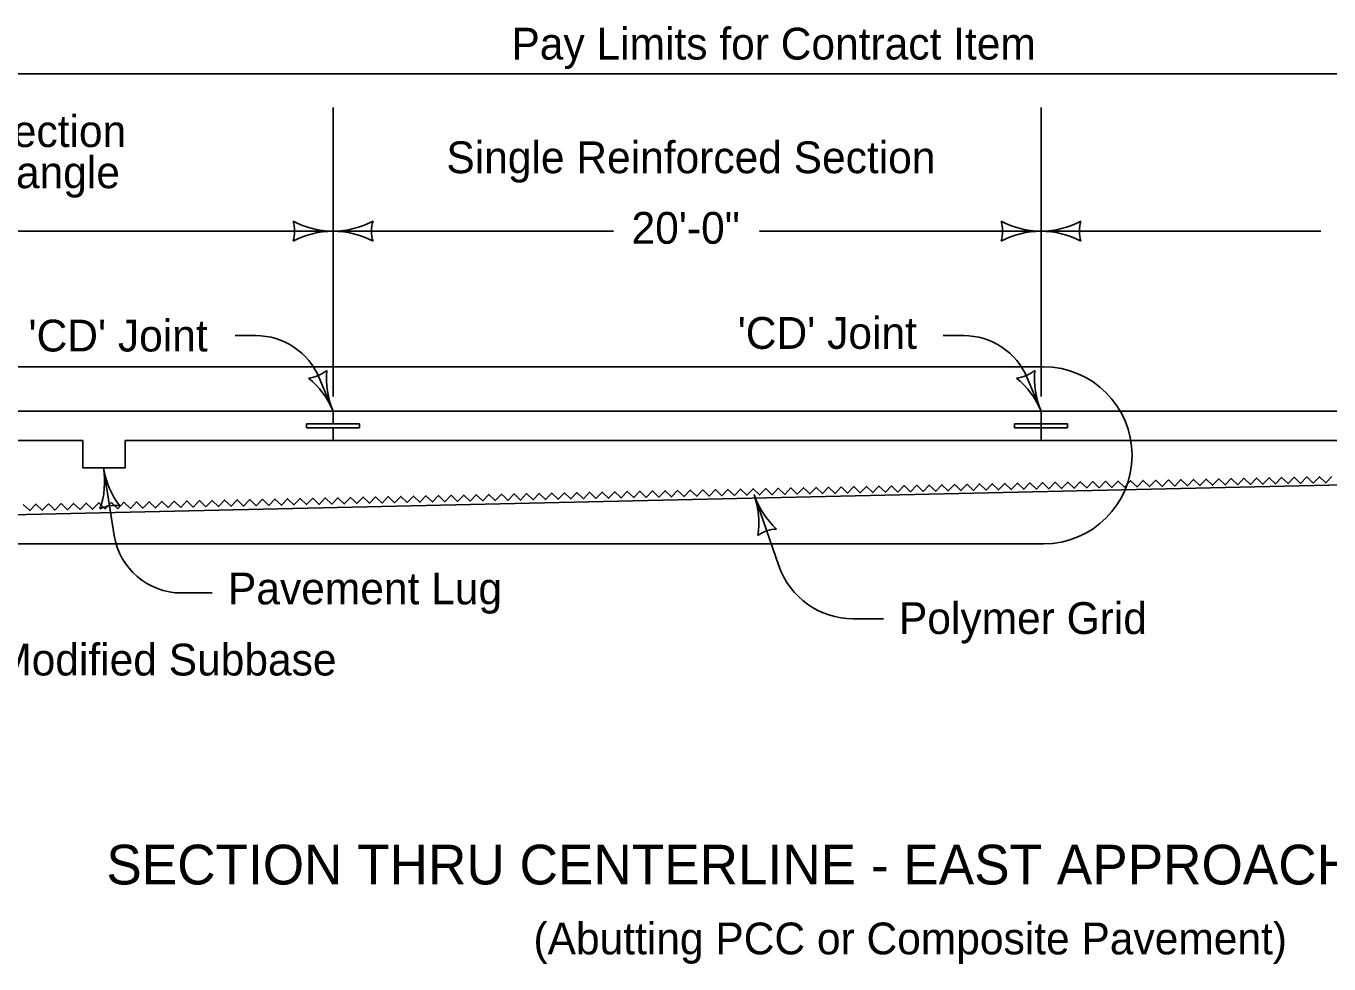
# Model space of a CAD drawing. Extents: x 5546 to 81668, y 3174 to 15999.
# Drawn here: x 14429 to 15084, y 8936 to 9408 of the extents above; entities that cross this region are included whole.
import ezdxf

# ---------------------------------------------------------------- set-up
doc = ezdxf.new("R2010")
doc.units = 0
for name, color, linetype in [('PS_BOLT', 7, 'Continuous'), ('PS_CONST', 7, 'Continuous'), ('PS_DAWA', 7, 'Continuous'), ('PS_DIM', 7, 'Continuous'), ('PS_SHAPE', 7, 'Continuous')]:
    doc.layers.add(name, color=color, linetype=linetype)

msp = doc.modelspace()

# ---------------------------------------------------------------- linework, layer by layer
at = {"layer": 'PS_BOLT'}
for p, q in [((14137.63, 9214.55), (14583.13, 9214.56)), ((14583.13, 9214.56), (14583.13, 9208.07)), ((14583.13, 9208.07), (14583.13, 9214.56)), ((14583.13, 9214.56), (14939.53, 9214.56)), ((14939.53, 9214.56), (14939.53, 9208.06)), ((14583.13, 9208.07), (14569.76, 9208.06)), ((14569.76, 9208.06), (14583.13, 9208.07)), ((14569.76, 9208.06), (14569.76, 9206.2)), ((14596.49, 9208.06), (14569.76, 9208.06)), ((14569.76, 9208.06), (14569.76, 9206.2)), ((14569.76, 9206.2), (14583.11, 9206.2)), ((14583.11, 9206.2), (14583.13, 9199.71)), ((14583.13, 9199.71), (14583.11, 9206.2)), ((14596.49, 9208.06), (14583.13, 9208.06)), ((14583.13, 9206.17), (14596.49, 9206.2)), ((14596.49, 9206.2), (14596.49, 9208.06)), ((14596.49, 9206.2), (14596.49, 9208.06)), ((14939.53, 9208.06), (14926.16, 9208.06)), ((14926.16, 9208.06), (14926.16, 9206.2)), ((14926.16, 9206.2), (14939.53, 9206.2)), ((14939.53, 9206.2), (14939.53, 9199.71)), ((14939.53, 9199.71), (14583.13, 9199.71))]:
    msp.add_line(p, q, dxfattribs=at)
msp.add_lwpolyline([(14583.13, 9199.71), (14478.47, 9199.71), (14478.47, 9185.96), (14457.23, 9185.96), (14457.23, 9199.71), (14174.75, 9199.71)], dxfattribs=at)
at = {"layer": 'PS_CONST'}
for p, q in [((14533.86, 9252.56), (14544.2, 9252.56)), ((14890.26, 9252.56), (14900.6, 9252.56)), ((14137.63, 9236.83), (14940.79, 9236.83)), ((14576.2, 9231.21), (14583.13, 9214.56)), ((14932.6, 9231.21), (14939.53, 9214.56)), ((14473, 9151.9), (14467.61, 9185.96)), ((14807.56, 9136.59), (14795.07, 9172.53)), ((14137.63, 9147.73), (14940.79, 9147.73)), ((14522.35, 9122.99), (14506.85, 9122.99)), ((14860.3, 9110), (14844.97, 9110))]:
    msp.add_line(p, q, dxfattribs=at)
for centre, radius, start, end in [((14544.21, 9217.9), 34.65, 22.59071, 90), ((14900.61, 9217.9), 34.65, 22.59071, 90), ((14569.36, 9247.65), 16.51, 274.85846, 310.32516), ((14622.6, 9230.98), 42.75, 174.51932, 202.59181), ((14925.76, 9247.65), 16.51, 274.85846, 310.32516), ((14979, 9230.98), 42.75, 174.51932, 202.59181), ((14940.79, 9192.28), 44.55, 270.00108, 90), ((14543.66, 9198.13), 42.75, 22.59181, 50.6643), ((14900.06, 9198.13), 42.75, 22.59181, 50.6643), ((14425.39, 9179.28), 42.75, 340.91683, 8.98932), ((14509.83, 9192.63), 42.75, 188.98932, 217.06181), ((14835.44, 9186.57), 42.75, 199.17509, 227.24758), ((14754.69, 9158.49), 42.75, 351.1026, 19.17509), ((14473.21, 9150.55), 16.51, 81.25597, 116.72267), ((14506.85, 9157.26), 34.27, 188.98933, 270), ((14806.84, 9138.68), 16.51, 91.44174, 126.90844), ((14844.97, 9149.6), 39.6, 199.1769, 270)]:
    msp.add_arc(centre, radius, start, end, dxfattribs=at)
at = {"layer": 'PS_DAWA'}
for p, q in [((14137.63, 9384.31), (15490.29, 9384.36)), ((14583.13, 9221.98), (14583.13, 9367.31)), ((14939.53, 9221.98), (14939.53, 9367.31)), ((14411.1, 9305.11), (14583.13, 9305.11)), ((14583.13, 9305.11), (14724.29, 9305.11)), ((14797.82, 9305.11), (14939.53, 9305.11)), ((14939.53, 9305.11), (15080.32, 9305.11))]:
    msp.add_line(p, q, dxfattribs=at)
for centre, radius, start, end in [((14547.29, 9305.12), 16.51, 342.26665, 17.73335), ((14583.13, 9347.87), 42.75, 241.92751, 270), ((14583.13, 9347.87), 42.75, 270, 298.07249), ((14618.97, 9305.12), 16.51, 162.26665, 197.73335), ((14903.69, 9305.12), 16.51, 342.26665, 17.73335), ((14939.53, 9347.87), 42.75, 241.92751, 270), ((14939.53, 9347.87), 42.75, 270, 298.07249), ((14975.37, 9305.12), 16.51, 162.26665, 197.73335), ((14583.13, 9262.37), 42.75, 90, 118.07249), ((14583.13, 9262.37), 42.75, 61.92751, 90), ((14939.53, 9262.37), 42.75, 90, 118.07249), ((14939.53, 9262.37), 42.75, 61.92751, 90)]:
    msp.add_arc(centre, radius, start, end, dxfattribs=at)
at = {"layer": 'PS_DIM'}
for p, q in [((14137.63, 9214.56), (15292.54, 9214.56)), ((14583.13, 9214.56), (14583.13, 9208.06)), ((15292.54, 9214.56), (14939.52, 9214.56)), ((14939.52, 9214.56), (14939.52, 9208.06)), ((14939.53, 9214.56), (14939.53, 9199.71)), ((14569.76, 9208.06), (14596.49, 9208.06)), ((14569.76, 9208.06), (14569.76, 9206.2)), ((14569.76, 9208.06), (14596.49, 9208.06)), ((14569.76, 9206.2), (14596.49, 9206.2)), ((14569.76, 9206.2), (14596.49, 9206.2)), ((14583.13, 9199.71), (14583.13, 9206.17)), ((14596.49, 9208.06), (14596.49, 9206.2)), ((14596.49, 9208.06), (14596.49, 9206.2)), ((14926.16, 9208.06), (14952.89, 9208.06)), ((14926.16, 9208.06), (14926.16, 9206.2)), ((14926.16, 9206.2), (14952.89, 9206.2)), ((14939.52, 9208.06), (14952.89, 9208.06)), ((14952.89, 9206.2), (14939.52, 9206.2)), ((14939.52, 9206.2), (14939.52, 9199.71)), ((14952.89, 9208.06), (14952.89, 9206.2)), ((14952.89, 9208.06), (14952.89, 9206.2)), ((14457.23, 9199.71), (14137.63, 9199.71)), ((15278.86, 9199.71), (14478.47, 9199.71)), ((14939.52, 9199.71), (15278.85, 9199.71)), ((15288.5, 9181.89), (14171.27, 9156.64))]:
    msp.add_line(p, q, dxfattribs=at)
for points in [[(14939.52, 9214.56), (14939.52, 9214.56)], [(14457.23, 9199.71), (14457.23, 9185.96), (14478.47, 9185.96), (14478.47, 9199.71)]]:
    msp.add_lwpolyline(points, dxfattribs=at)
at = {"layer": 'PS_SHAPE'}
for points in [[(14745.55, 9172.8), (14747.17, 9171.25), (14750.27, 9174.48), (14753.51, 9171.38), (14756.61, 9174.62), (14759.84, 9171.52), (14762.94, 9174.75), (14766.18, 9171.65), (14769.27, 9174.89), (14772.51, 9171.79), (14775.61, 9175.03), (14778.84, 9171.93), (14781.95, 9175.16), (14785.18, 9172.06), (14788.28, 9175.3), (14791.51, 9172.2), (14794.61, 9175.43), (14797.85, 9172.33), (14800.95, 9175.56), (14804.18, 9172.47), (14807.28, 9175.7), (14810.52, 9172.6), (14813.62, 9175.84), (14816.85, 9172.74), (14819.95, 9175.97), (14821.57, 9174.43)], [(14821.57, 9174.43), (14823.19, 9172.87), (14826.29, 9176.11), (14829.52, 9173.01), (14832.62, 9176.25), (14835.86, 9173.15), (14838.95, 9176.38), (14842.19, 9173.28), (14845.29, 9176.52), (14848.52, 9173.42), (14851.63, 9176.65), (14854.86, 9173.55), (14857.96, 9176.78), (14861.19, 9173.69), (14864.29, 9176.92), (14867.53, 9173.82), (14870.63, 9177.06), (14873.86, 9173.96), (14876.96, 9177.19), (14880.2, 9174.09), (14883.3, 9177.33), (14886.53, 9174.23), (14889.63, 9177.47), (14892.87, 9174.37), (14895.97, 9177.6), (14897.59, 9176.05)], [(14897.59, 9176.05), (14899.2, 9174.5), (14902.3, 9177.73), (14905.54, 9174.63), (14908.63, 9177.87), (14911.87, 9174.77), (14914.97, 9178), (14918.2, 9174.91), (14921.31, 9178.14), (14924.54, 9175.04), (14927.64, 9178.28), (14930.87, 9175.18), (14933.97, 9178.41), (14937.21, 9175.31), (14940.31, 9178.55), (14943.54, 9175.45), (14946.64, 9178.69), (14949.88, 9175.58), (14952.98, 9178.82), (14956.21, 9175.72), (14959.31, 9178.95), (14962.55, 9175.85), (14965.65, 9179.09), (14968.88, 9175.99), (14971.98, 9179.22), (14973.6, 9177.68)], [(14973.6, 9177.68), (14975.22, 9176.13), (14978.31, 9179.36), (14981.55, 9176.26), (14984.65, 9179.5), (14987.88, 9176.4), (14990.99, 9179.63), (14994.22, 9176.53), (14997.32, 9179.77), (15000.55, 9176.67), (15003.65, 9179.91), (15006.89, 9176.8), (15009.99, 9180.04), (15013.22, 9176.94), (15016.32, 9180.17), (15019.56, 9177.07), (15022.66, 9180.31), (15025.89, 9177.21), (15028.99, 9180.44), (15032.23, 9177.35), (15035.33, 9180.58), (15038.56, 9177.48), (15041.66, 9180.72), (15044.9, 9177.62), (15047.99, 9180.85), (15049.61, 9179.3)], [(15049.61, 9179.3), (15051.23, 9177.75), (15054.33, 9180.99), (15057.56, 9177.89), (15060.67, 9181.13), (15063.9, 9178.02), (15067, 9181.26), (15070.23, 9178.16), (15073.33, 9181.39), (15076.57, 9178.29), (15079.67, 9181.53), (15082.9, 9178.43), (15086, 9181.66)], [(14441.5, 9166.29), (14443.11, 9164.74), (14446.21, 9167.98), (14449.45, 9164.88), (14452.55, 9168.11), (14455.78, 9165.02), (14458.88, 9168.25), (14462.12, 9165.15), (14465.22, 9168.38), (14468.45, 9165.29), (14471.55, 9168.52), (14474.78, 9165.42), (14477.89, 9168.66), (14481.12, 9165.55), (14484.22, 9168.79), (14487.46, 9165.69), (14490.55, 9168.93), (14493.79, 9165.83), (14496.89, 9169.06), (14500.12, 9165.96), (14503.23, 9169.2), (14506.46, 9166.1), (14509.56, 9169.33), (14512.79, 9166.24), (14515.89, 9169.47), (14517.51, 9167.92)], [(14517.51, 9167.92), (14519.13, 9166.37), (14522.23, 9169.6), (14525.46, 9166.51), (14528.56, 9169.74), (14531.8, 9166.64), (14534.9, 9169.88), (14538.13, 9166.77), (14541.23, 9170.01), (14544.46, 9166.91), (14547.57, 9170.15), (14550.8, 9167.05), (14553.9, 9170.28), (14557.14, 9167.18), (14560.23, 9170.42), (14563.47, 9167.32), (14566.57, 9170.55), (14569.8, 9167.46), (14572.91, 9170.69), (14576.14, 9167.59), (14579.24, 9170.82), (14582.47, 9167.72), (14585.57, 9170.96), (14588.81, 9167.86), (14591.91, 9171.09), (14593.53, 9169.55)], [(14593.53, 9169.55), (14595.14, 9167.99), (14598.24, 9171.23), (14601.48, 9168.13), (14604.58, 9171.37), (14607.81, 9168.27), (14610.91, 9171.5), (14614.15, 9168.4), (14617.25, 9171.64), (14620.48, 9168.54), (14623.58, 9171.77), (14626.82, 9168.67), (14629.91, 9171.91), (14633.15, 9168.81), (14636.25, 9172.04), (14639.48, 9168.94), (14642.59, 9172.18), (14645.82, 9169.08), (14648.92, 9172.31), (14652.15, 9169.21), (14655.25, 9172.45), (14658.49, 9169.35), (14661.59, 9172.59), (14664.82, 9169.49), (14667.92, 9172.72), (14669.54, 9171.17)], [(14669.54, 9171.17), (14671.16, 9169.62), (14674.26, 9172.86), (14677.49, 9169.76), (14680.59, 9172.99), (14683.83, 9169.89), (14686.93, 9173.13), (14690.16, 9170.03), (14693.26, 9173.26), (14696.5, 9170.16), (14699.59, 9173.4), (14702.83, 9170.3), (14705.93, 9173.53), (14709.16, 9170.43), (14712.27, 9173.67), (14715.5, 9170.57), (14718.6, 9173.81), (14721.83, 9170.71), (14724.93, 9173.94), (14728.17, 9170.84), (14731.27, 9174.08), (14734.5, 9170.98), (14737.6, 9174.21), (14740.84, 9171.11), (14743.94, 9174.35), (14745.55, 9172.8)], [(14427.21, 9167.57), (14430.44, 9164.47), (14433.54, 9167.71), (14436.78, 9164.61), (14439.88, 9167.84), (14441.5, 9166.29)]]:
    msp.add_lwpolyline(points, dxfattribs=at)

# ---------------------------------------------------------------- texts
at = {"layer": 'PS_BOLT'}
msp.add_text('SECTION THRU CENTERLINE - EAST APPROACH PAVEMENT', height=20, dxfattribs=at).set_placement((14469.01, 8976.26))
at = {"layer": 'PS_CONST'}
for s, p in [("'CD' Joint", (14429.81, 9244.56)), ("'CD' Joint", (14786.83, 9245.89)), ('Pavement Lug', (14530.24, 9117.29)), ('Polymer Grid', (14868.02, 9102.35)), ('Modified Subbase', (14413.6, 9081.46))]:
    msp.add_text(s, height=16, dxfattribs=at).set_placement(p)
at = {"layer": 'PS_DAWA'}
for s, p in [('Pay Limits for Contract Item', (14672.95, 9391.52)), ('Double Reinforced Section', (14224.49, 9347.48)), ('Single Reinforced Section', (14640.19, 9334.31)), ('as required by skew angle', (14227.29, 9326.77)), ('20\'-0"', (14733.4, 9298.79))]:
    msp.add_text(s, height=16, dxfattribs=at).set_placement(p)
at = {"layer": 'PS_SHAPE'}
msp.add_text('(Abutting PCC or Composite Pavement)', height=16, dxfattribs=at).set_placement((14684.02, 8941.08))

doc.saveas('drawing.dxf')
